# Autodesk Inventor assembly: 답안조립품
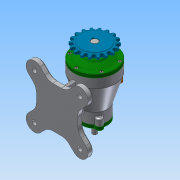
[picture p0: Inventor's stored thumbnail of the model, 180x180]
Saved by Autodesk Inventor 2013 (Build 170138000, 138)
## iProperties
Created: 2018-03
Part Number: 답안조립품
Document SubType Name: Assembly
Designer: Administrator
Author: Administrator
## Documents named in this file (15)
- C:\Users\Administrator\Desktop\480308V1017\답안조립품.iam
- C:\Users\Administrator\Desktop\480308V1017\뒤커버.ipt
- C:\Users\Administrator\Desktop\480308V1017\마개.ipt
- C:\Users\Administrator\Desktop\480308V1017\베어링-6200.ipt
- C:\Users\Administrator\Desktop\480308V1017\베어링-6203.ipt
- C:\Users\Administrator\Desktop\480308V1017\본체.ipt
- C:\Users\Administrator\Desktop\480308V1017\볼트 M4 x 12.ipt
- 볼트 M4 x 12.ipt
- C:\Users\Administrator\Desktop\480308V1017\스프로킷.ipt
- C:\Users\Administrator\Desktop\480308V1017\앞커버.ipt
- C:\Users\Administrator\Desktop\480308V1017\오일 실 10 20 7.ipt
- C:\Users\Administrator\Desktop\480308V1017\오일 실 17 30 8.ipt
- C:\Users\Administrator\Desktop\480308V1017\축.ipt
- C:\Users\Administrator\Desktop\480308V1017\키 5 x 5.ipt
- 키 5 x 5.ipt
